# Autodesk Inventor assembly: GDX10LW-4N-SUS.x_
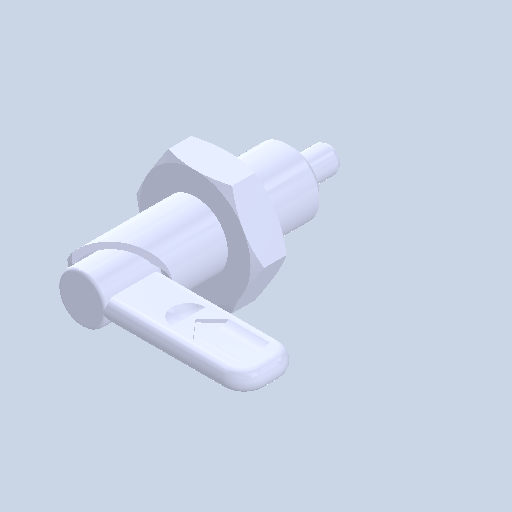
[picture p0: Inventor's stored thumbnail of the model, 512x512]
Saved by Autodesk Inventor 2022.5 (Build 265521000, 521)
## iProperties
Created: 2024-06
Part Number: GDX10LW-4N-SUS.x_
Document SubType Name: Assembly
Designer: ImaoCorp
Author: ImaoCorp
Sending System: SOLIDWORKS 2022-2022290
MC: AMD64
MC_MODEL: Intel64 Family 6 Model 60 Stepping 3, GenuineIntel
OS: Windows_NT
FRU: Parasolid Version 33.1, build 260,  4-25-2022
FORMAT: text
GUISE: transmit
KEY: FILEGDX10LW-4N-SUS.x_t
DATE: Wed Jun 12 09:31:26 2024
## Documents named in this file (4)
- Y:\5.更新分\2024年対応\xxxx_GDX\データ_imao品番\gdx10lw-4n-sus\GDX10LW-4N-SUS.x_.iam
- Y:\5.更新分\2024年対応\xxxx_GDX\データ_imao品番\gdx10lw-4n-sus\GDX10LW-4N-SUS_01.ipt
- Y:\5.更新分\2024年対応\xxxx_GDX\データ_imao品番\gdx10lw-4n-sus\GDX10LW-4N-SUS_02.ipt
- Y:\5.更新分\2024年対応\xxxx_GDX\データ_imao品番\gdx10lw-4n-sus\GDX10LW-4N-SUS_03.ipt
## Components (3 placed, 3 different names)
1. GDX10LW-4N-SUS_01
2. GDX10LW-4N-SUS_02
3. GDX10LW-4N-SUS_03
